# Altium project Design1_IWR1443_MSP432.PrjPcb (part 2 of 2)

## Sheet Design1_HighVoltage.SchDoc: High Voltage Management
size 431 x 279 mm; Date: Not shown in title block; ApprovedBy: Not shown in title block; CheckedBy: Not shown in title block; Author: Not shown in title block; CompanyName: Not shown in title block; DrawnBy: Joe Quintal; Engineer: Not shown in title block; Organization: Not shown in title block; Address1: Not shown in title block; Address2: Not shown in title block; Address3: Not shown in title block; Address4: Not shown in title block; DocumentNumber: 5; Revision: Use project parameter SCH_Rev; SheetNumber: 5; SheetTotal: 6; PageSetup: Record=PageOptions¦CenterHorizontal=True¦CenterVertical=True¦PrintScale=0.64¦XCorrection=1.00¦YCorrection=1.00¦PrintKind=0¦BorderSize=5000000¦LeftOffset=0¦BottomOffset=0¦Orientation=2¦PaperLength=1000¦PaperWidth=1000¦Scale=100¦PaperSource=15¦PrintQuality=600¦MediaType=1¦DitherType=10¦PrintScaleMode=1¦PaperKind=Letter
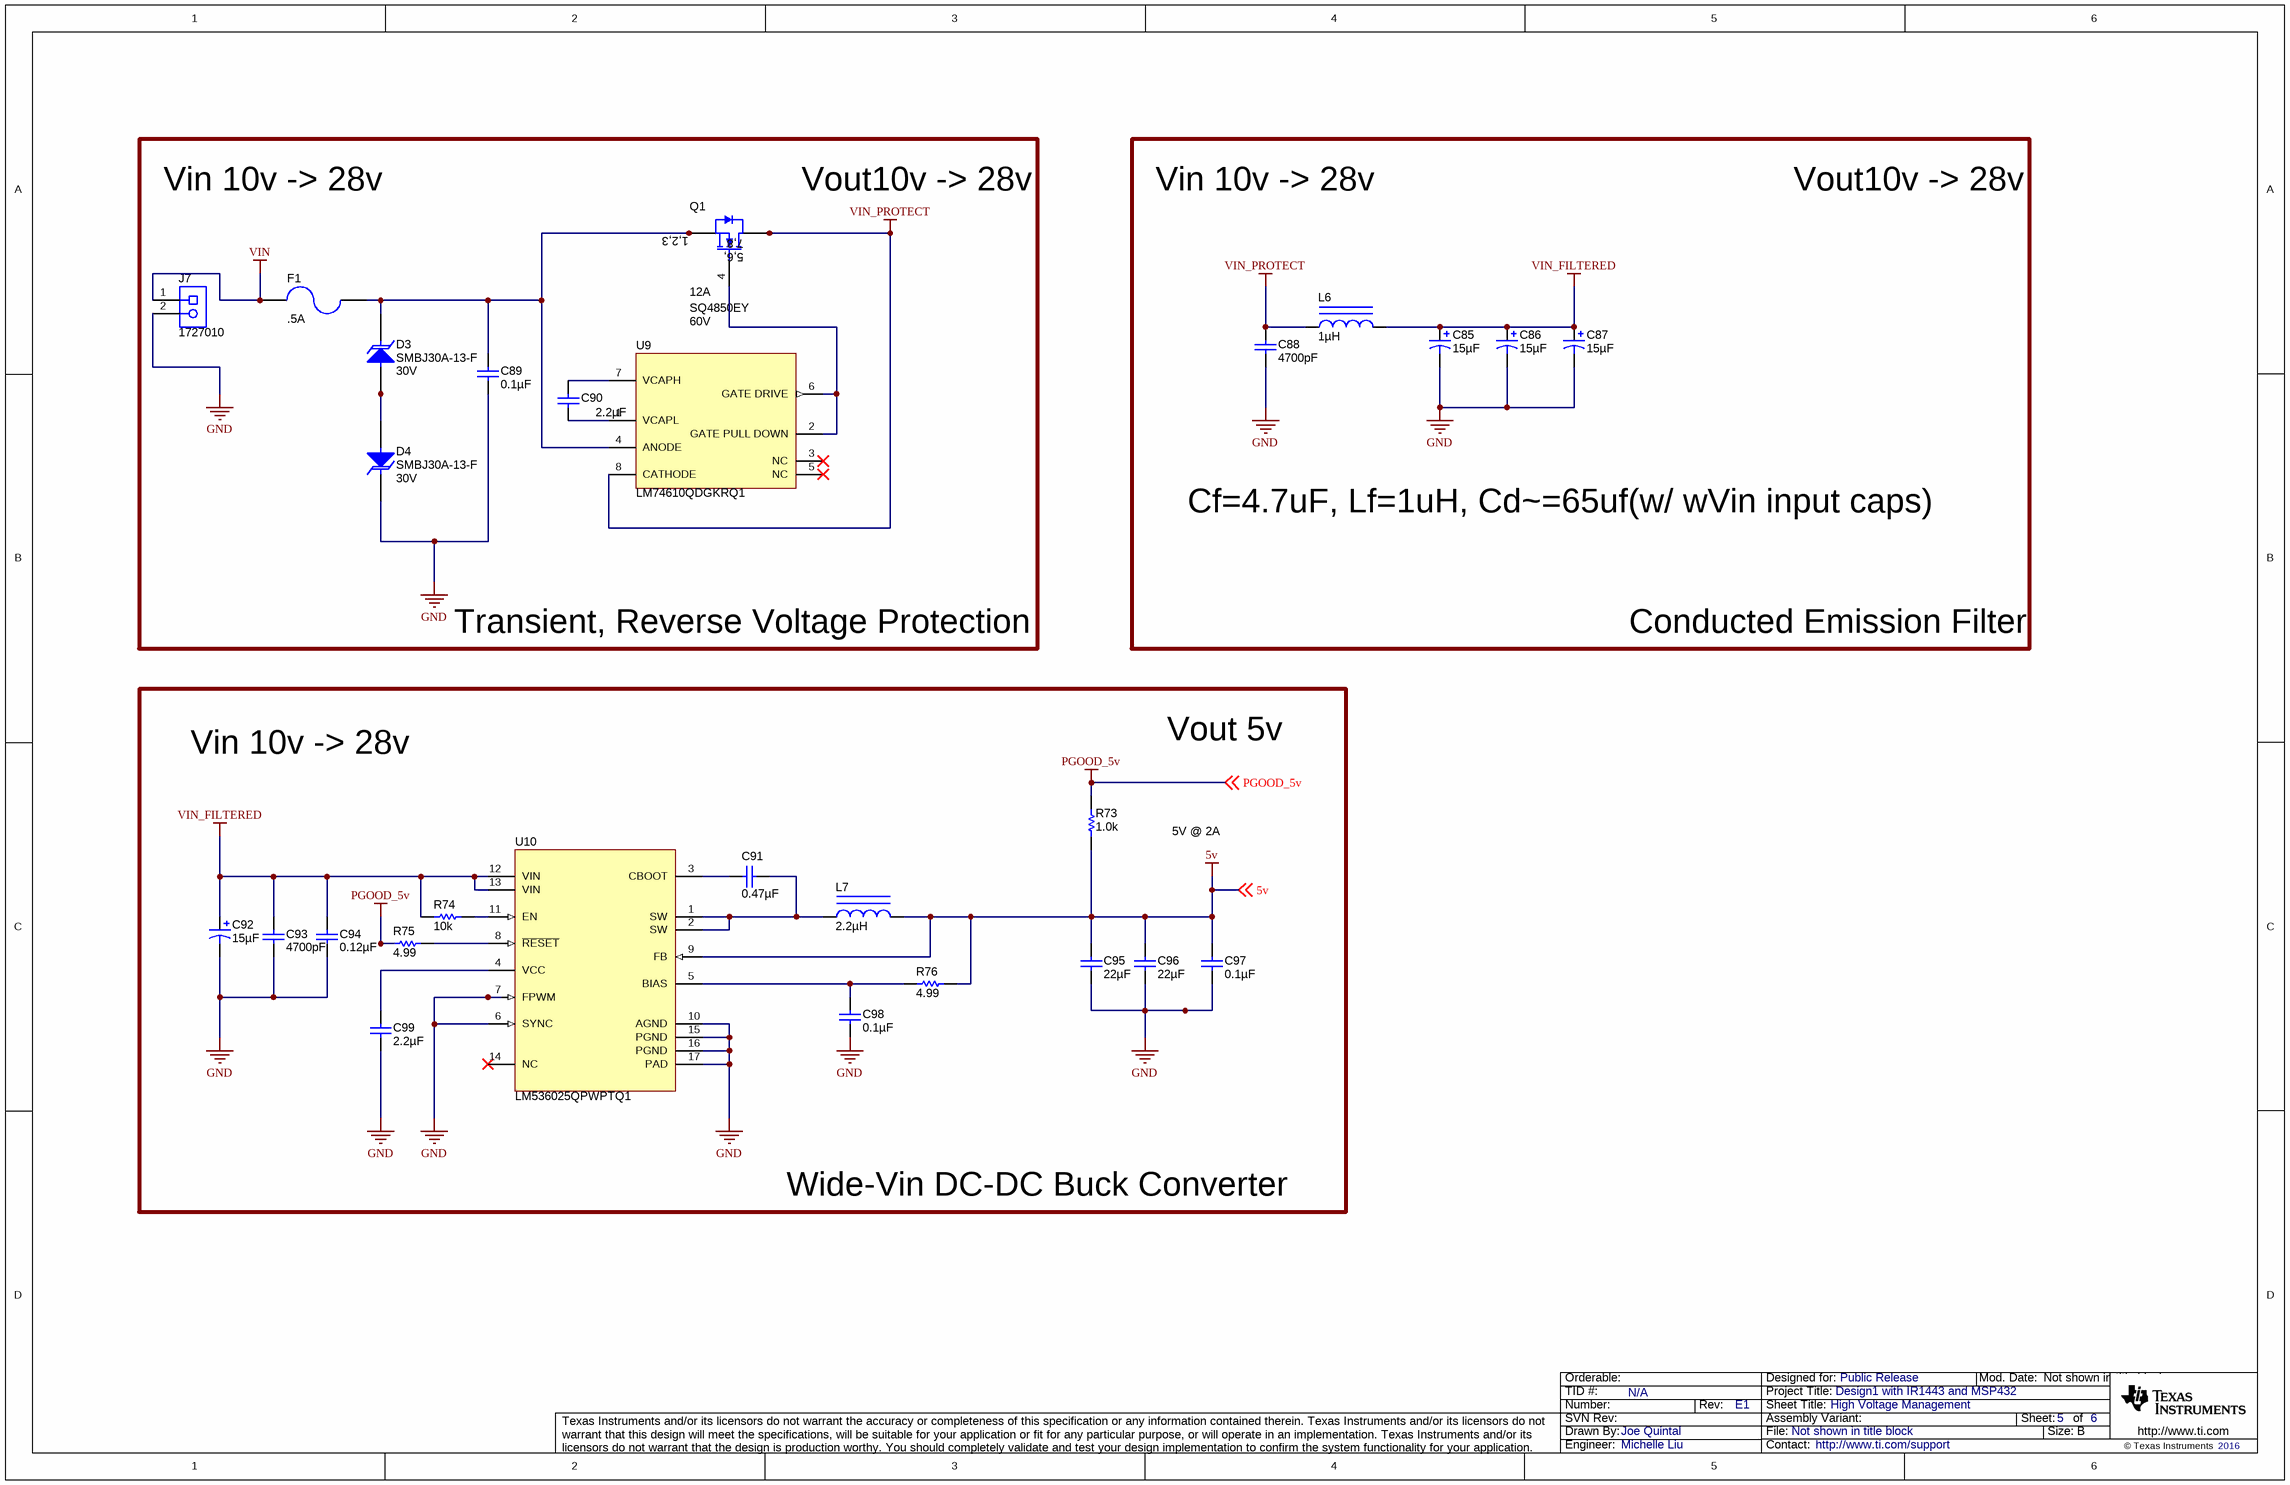
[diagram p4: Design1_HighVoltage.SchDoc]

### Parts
C85  ValueDisplayed: 15µF  [CC_CASER]  (hidden comment: TPSE156M050T0250V)
C86  ValueDisplayed: 15µF  [CC_CASER]  (hidden comment: TPSE156M050T0250V)
C87  ValueDisplayed: 15µF  [CC_CASER]  (hidden comment: TPSE156M050T0250V)
C88  ValueDisplayed: 4700pF  [0603]  (hidden comment: 885012206087)
C89  ValueDisplayed: 0.1µF  [0805_145]  (hidden comment: CEU4J2X7R1H104K125AE)
C90  ValueDisplayed: 2.2µF  [0603]  (hidden comment: GRM188R71A225KE15D)
C91  ValueDisplayed: 0.47µF  [0603S]  (hidden comment: GRM188R71E474KA12D)
C92  ValueDisplayed: 15µF  [CC_CASER]  (hidden comment: TPSE156M050T0250V)
C93  ValueDisplayed: 4700pF  [0805_HV]  (hidden comment: 08055C472JAT2A)
C94  ValueDisplayed: 0.12µF  [0805_HV]  (hidden comment: 08055C124KAT2A)
C95  ValueDisplayed: 22µF  [0805_HV]  (hidden comment: EMK212BBJ226MG-T)
C96  ValueDisplayed: 22µF  [0805_HV]  (hidden comment: EMK212BBJ226MG-T)
C97  ValueDisplayed: 0.1µF  [0402]  (hidden comment: GRM155R61C104KA88D)
C98  ValueDisplayed: 0.1µF  [0402S]  (hidden comment: GCM155R7IC104KA55D)
C99  ValueDisplayed: 2.2µF  [0603S]  (hidden comment: GRM188R71A225KE15D)
D3  SMBJ30A-13-F  value 30V  [SMB]
D4  SMBJ30A-13-F  value 30V  [SMB]
F1  .5A  [1812]
J7  1727010  [PhoenixConact_1727010]
L6  ValueDisplayed: 1µH  [IFSC-0806AZ-01]  (hidden comment: IFSC0806AZER1R0M01)
L7  ValueDisplayed: 2.2µH  [IHLP-2020BZ]  (hidden comment: IHLP2020BZER2R2M01)
Q1  12A  value 60V  [SO-8]
R73  ValueDisplayed: 1.0k  [0603]  (hidden comment: CRCW06031K00JNEA)
R74  ValueDisplayed: 10k  [0402S]  (hidden comment: CRCW040210K0JNED)
R75  ValueDisplayed: 4.99  [0402S]  (hidden comment: CRCW04024R99FKED)
R76  ValueDisplayed: 4.99  [0402S]  (hidden comment: CRCW04024R99FKED)
U9  LM74610QDGKRQ1  [DGK0008A_N]
U10  LM536025QPWPTQ1  [PWP0016H_N]

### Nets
5v: C95.1 C96.1 C97.1 L7.2 R73.1 R76.2 U10.9(FB) ; off-sheet 5v
GND: C85.2(-) C86.2(-) C87.2(-) C88.2 C89.2 C92.2(-) C93.1 C94.2 C95.2 C96.2 C97.2 C98.2 C99.2 D4.1(K) J7.2 U10.6(SYNC) U10.7(FPWM) U10.10(AGND) U10.15(PGND) U10.16(PGND) U10.17(PAD)
PGOOD_5v: R73.2 R75.1 ; off-sheet PGOOD_5v
VIN: F1.2 J7.1
VIN_FILTERED: C85.1(+) C86.1(+) C87.1(+) C92.1(+) C93.2 C94.1 L6.2 R74.1 U10.12(VIN) U10.13(VIN)
VIN_PROTECT: C88.1 L6.1 Q1.5(D) Q1.6(D) Q1.7(D) Q1.8(D) U9.8(CATHODE)
NetC89_1: C89.1 D3.1(K) F1.1 Q1.1(S) Q1.2(S) Q1.3(S) U9.4(ANODE)
NetC90_1: C90.1 U9.7(VCAPH)
NetC90_2: C90.2 U9.1(VCAPL)
NetC91_1: C91.1 L7.1 U10.1(SW) U10.2(SW)
NetC91_2: C91.2 U10.3(CBOOT)
NetC98_1: C98.1 R76.1 U10.5(BIAS)
NetC99_1: C99.1 U10.4(VCC)
NetD3_2: D3.2(A) D4.2(A)
NetQ1_4: Q1.4(G) U9.2(GATE_PULL_DOWN) U9.6(GATE_DRIVE)
NetR74_2: R74.2 U10.11(EN)
NetR75_2: R75.2 U10.8(~{RESET})

Not connected (* = marked no-connect by the designer): U9 3(NC)* 5(NC)*; U10 14(NC)*

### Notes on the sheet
- Vin 10v -> 28v
- Vout10v -> 28v
- Cf=4.7uF, Lf=1uH, Cd~=65uf(w/ wVin input caps)
- Transient, Reverse Voltage Protection
- Conducted Emission Filter
- Vout 5v
- 5V @ 2A
- Wide-Vin DC-DC Buck Converter

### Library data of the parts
C85-C87 C92 = 595D226X0050R2T: CAP, TA, 15 µF, 50 V, +/- 20%, 0.25 ohm, SMD; Manufacturer: AVX; Polarized: Y; CompType: Capacitor; Value: 22uF; U/M: EA; Cap_F: 0.000022; Tolerance_%: 20; Value1: 0.39 ohm; VDC_V: 50; Value2: 50V; ESR_ohm: .25; TaMin_C: -55; TaMax_C: 85; Cap_Case: E; SizeAreaWB_mm2: 73.6; SizeArea_mm2: 43.2; SizeX_mm: 7.2; SizeY_mm: 6; SizeZ_mm: 3.5
C88 = 885012206087: CAP, CERM, 4700 pF, 50 V, +/- 10%, X7R, 0603; Manufacturer: Wurth Elektronik; Polarized: N; CompType: Capacitor; Value: 4700pF; U/M: EA; Cap_F: 0.0000000047; Tolerance_%: 10; Value1: Unknown; VDC_V: 50; Value2: 50V; TaMin_C: -55; TaMax_C: 125; SizeArea_mm2: 1.28; SizeAreaWB_mm2: 4.68; SizeX_mm: 1.6; SizeY_mm: 0.8; SizeZ_mm: 1; AEC Category: Q200
C89 = CEU4J2X7R1H104K125AE: CAP, CERM, 0.1 µF, 50 V, +/- 10%, X7R, 0805; Manufacturer: TDK; Polarized: N; CompType: Capacitor; Value: 0.1uF; U/M: EA; Cap_F: 0.0000001; Tolerance_%: 10; Value1: Unknown; VDC_V: 50; Value2: 50V; TaMin_C: -55; TaMax_C: 125; Cap_Case: 0805
C90 = GRM188R71A225KE15D: CAP, CERM, 2.2 µF, 10 V, +/- 10%, X7R, 0603; Manufacturer: MuRata; Polarized: N; CompType: Capacitor; Value: 2.2uF; U/M: EA; Cap_F: 0.0000022; Tolerance_%: 10; ESR_ohm: 0.009; Value1: 0.009 ohm; Value2: 10V; TaMin_C: -55; TaMax_C: 125
C91 = GRM188R71E474KA12D: CAP, CERM, 0.47 µF, 25 V, +/- 10%, X7R, 0603; Manufacturer: MuRata; Polarized: N; CompType: Capacitor; Value: 0.47uF; U/M: EA; Cap_F: 0.00000047; Tolerance_%: 10; Value1: Unknown; VDC_V: 25; Value2: 25V; TaMin_C: -55; TaMax_C: 125; Cap_Case: 0603
C93 = 08055C472JAT2A: CAP, CERM, 4700 pF, 50 V, +/- 5%, X7R, 0805; Manufacturer: AVX; Polarized: N; CompType: Capacitor; Value: 4700pF; U/M: EA; Cap_F: 0.0000000047; Tolerance_%: 5; ESR_ohm: 0.119; Value1: 0.119 ohm; VDC_V: 50; Value2: 50V; TaMin_C: -55; TaMax_C: 125; Cap_Case: 0805; SizeArea_mm2: 2.5; SizeAreaWB_mm2: 6.75; SizeX_mm: 2; SizeY_mm: 1.25; SizeZ_mm: 1.45; AEC Category: Q200
C94 = 08055C124KAT2A: CAP, CERM, 0.12 µF, 50 V, +/- 10%, X7R, 0805; Manufacturer: AVX; Polarized: N; CompType: Capacitor; Value: 0.12uF; U/M: EA; Cap_F: 0.00000012; Tolerance_%: 10; ESR_ohm: 0.022; Value1: 0.022 ohm; VDC_V: 50; Value2: 50V; TaMin_C: -55; TaMax_C: 125; Cap_Case: 0805; SizeArea_mm2: 2.5; SizeAreaWB_mm2: 6.75; SizeX_mm: 2; SizeY_mm: 1.25; SizeZ_mm: 1.45; AEC Category: Q200
C95 C96 = EMK212BBJ226MG-T: CAP, CERM, 22 µF, 16 V, +/- 20%, X5R, 0805; Manufacturer: Taiyo Yuden; Polarized: N; CompType: Capacitor; Value: 22uF; U/M: EA; Cap_F: 0.000022; Tolerance_%: 20; Value1: Unknown; VDC_V: 16; Value2: 16V; TaMin_C: -55; TaMax_C: 85; Cap_Case: 0805; SizeArea_mm2: 2.5; SizeAreaWB_mm2: 6.75; SizeX_mm: 2; SizeY_mm: 1.25; SizeZ_mm: 1.45; AEC Category: Q200
C97 = GRM155R61C104KA88D: CAP, CERM, 0.1 µF, 16 V, +/- 10%, X5R, 0402; Manufacturer: MuRata; Polarized: N; CompType: Capacitor; Value: 0.1uF; U/M: EA; Cap_F: 0.0000001; Tolerance_%: 10; Value1: Unknown; VDC_V: 16; Value2: 16V; TaMin_C: -55; TaMax_C: 85; SizeArea_mm2: 0.5; SizeAreaWB_mm2: 3; SizeX_mm: 1; SizeZ_mm: 0.6; AEC Category: Q200
C98 = GCM155R7IC104KA55D: CAP, CERM, 0.1 µF, 16 V, +/- 10%, X7R, 0402; Manufacturer: MuRata; Polarized: N; CompType: Capacitor; Value: 0.1uF; U/M: EA; Cap_F: 0.0000001; Tolerance_%: 10; Value1: Unknown; VDC_V: 16; Value2: 16V; TaMin_C: -55; TaMax_C: 125; Cap_Case: 0402
C99 = GRM188R71A225KE15D: CAP, CERM, 2.2 µF, 10 V, +/- 10%, X7R, 0603; Manufacturer: MuRata; Polarized: N; CompType: Capacitor; Value: 2.2uF; U/M: EA; Cap_F: 0.0000022; Tolerance_%: 10; ESR_ohm: 0.009; Value1: 0.009 ohm; Value2: 10V; TaMin_C: -55; TaMax_C: 125; Cap_Case: 0603
D3 D4 = SMBJ30A-13-F: Diode, TVS, Uni, 30 V, 48.4 Vc, SMB; Manufacturer: Diodes Inc.; U/M: EA; Power_W: 5; Vr_V: 30; Value1: 5W; SizeAreaWB_mm2: 44.156; SizeArea_mm2: 21.336; SizeX_mm: 5.6; SizeY_mm: 3.81; SizeZ_mm: 2.6; AEC Category: Q101
F1 = 0ZCC0075BF2B: Fuse, 0.75 A, 33 VDC, SMD; Manufacturer: Bel Fuse; SizeAreaWB_mm2: 23.1; SizeArea_mm2: 14.4; SizeX_mm: 4.5; SizeY_mm: 3.2; SizeZ_mm: 1.35; VDC_V: 33; Irating_A: 0.75; Rtyp_Ohm: 0.18
J7 = 1727010: Conn Term Block, 2POS, 3.81mm, TH; Manufacturer: Phoenix Contact; SymbolCreator: a0412235; CompType: Terminal Block; U/M: EA; Value: 2x1
L6 = IFSC0806AZER1R0M01: Inductor, Shielded, Ferrite, 1 µH, 1.6 A, 0.115 ohm, SMD; Manufacturer: Vishay-Dale; Value: 1uH; Ind_H: 1.0E-6; Imax_A: 1.6; Irms: 1.6A @ 40C rise; Isat: 1.88A @ 30% inductance drop; DCR_ohm: 0.115; Value2: 1.6A; SizeAreaWB_mm2: 7.8; SizeArea_mm2: 3.2; SizeX_mm: 2; SizeZ_mm: 1; AEC Category: Q200
L7 = IHLP2020BZER2R2M01: Inductor, Shielded Drum Core, Powdered Iron, 2.2 µH, 4.2 A, 0.0456 ohm, SMD; Manufacturer: Vishay-Dale; Value: 2.2uH; Ind_H: 2.2E-6; Imax_A: 4.2; Irms: 4.2A @ 40C rise; Isat: 12.5A @ 20% inductance drop; DCR_ohm: 0.0456; Value2: 4.2A; SizeAreaWB_mm2: 53.7782; SizeArea_mm2: 28.4382; SizeX_mm: 5.49; SizeY_mm: 5.18; SizeZ_mm: 2; AEC Category: Q200
Q1 = SQ4850EY: MOSFET, N-CH, 60 V, 12 A, SO-8; Manufacturer: Vishay-Siliconix; Alternate Manufacturer: None; U/M: EA; ChType: N; VdsMax_V: 60; Value1: 0.031 ohm; Rdson45_ohm: 0.031; Value2: 20 nC; QgTyp_nC: 20; IdsMax_A: 12
R73 = CRCW06031K00JNEA: RES, 1.0 k, 5%, 0.1 W, 0603; Manufacturer: Vishay-Dale; CompType: Resistor; Value: 1.0k; Res_ohm: 1000; Value_Code: 1k00; Tolerance_%: 5; Power_W: 0.1; Value2: 0.1W; VDC_V: 75; TempCo: 200 ppm/C; SizeArea_mm2: 1.28; SizeX_mm: 1.6; SizeY_mm: 0.8; SizeZ_mm: 1; EIA_Code: E24; U/M: EA; AEC Category: Q200
R74 = CRCW040210K0JNED: RES, 10 k, 5%, 0.063 W, 0402; Manufacturer: Vishay-Dale; CompType: Resistor; Value: 10k; Res_ohm: 10000; Value_Code: 10k0; Tolerance_%: 5; Power_W: 0.063; Value2: 0.063W; VDC_V: 50; TempCo: 200 ppm/C; EIA_Code: E24; U/M: EA
R75 R76 = CRCW04024R99FKED: RES, 4.99, 1%, 0.063 W, 0402; Manufacturer: Vishay-Dale; CompType: Resistor; Value: 4.99; Value_Code: 4R99; Tolerance_%: 1; Power_W: 0.063; Value2: 0.063W; VDC_V: 50; TempCo: 100 ppm/C; EIA_Code: E96; U/M: EA
U9 = LM74610QDGKRQ1: Smart Diode Controller, DGK0008A; Manufacturer: Texas Instruments; SymbolCreator: Altium; CompType: IC; U/M: EA
U10 = LM536033QPWPQ1: 5V, 2A, Buck Regulator For Automotive Applications, PWP0016H; Manufacturer: Texas Instruments; SymbolCreator: Altium; CompType: IC; U/M: EA

## Sheet Design1_EVM_Hardware.SchDoc
size 431 x 279 mm; Date: Not shown in title block; ApprovedBy: Not shown in title block; CheckedBy: Not shown in title block; Author: Not shown in title block; CompanyName: Not shown in title block; Engineer: Not shown in title block; Organization: Not shown in title block; Address1: Not shown in title block; Address2: Not shown in title block; Address3: Not shown in title block; Address4: Not shown in title block; DocumentNumber: 6; Revision: Use project parameter SCH_Rev; SheetNumber: 6; SheetTotal: 6; PageSetup: Record=PageOptions¦CenterHorizontal=True¦CenterVertical=True¦PrintScale=1.00¦XCorrection=1.00¦YCorrection=1.00¦PrintKind=0¦BorderSize=5000000¦LeftOffset=0¦BottomOffset=0¦Orientation=2¦PaperLength=1000¦PaperWidth=1000¦Scale=100¦PaperSource=15¦PrintQuality=600¦MediaType=1¦DitherType=10¦PaperKind=Letter¦PrintScaleMode=1
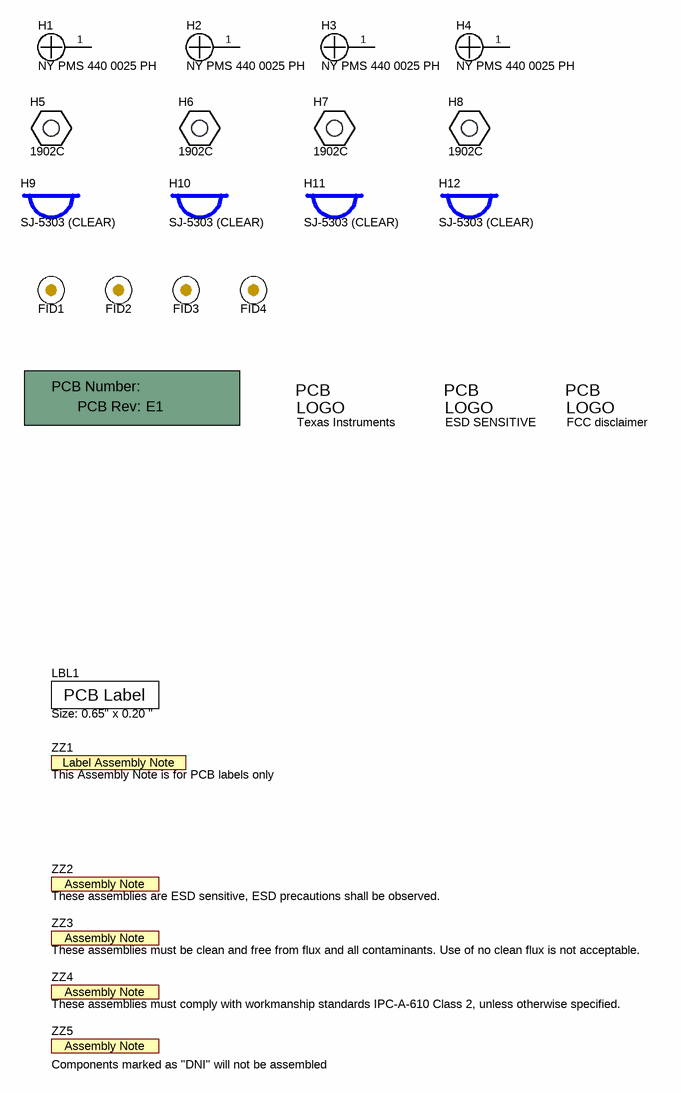
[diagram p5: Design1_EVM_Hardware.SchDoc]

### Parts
!PCB1  Printed Circuit Board  (value not drawn)  (mechanical)
FID1  Fiducial  [Fiducial10-20]  (value not drawn)
FID2  Fiducial  [Fiducial10-20]  (value not drawn)
FID3  Fiducial  [Fiducial10-20]  (value not drawn)
FID4  Fiducial  [Fiducial10-20]  (value not drawn)
H1  NY PMS 440 0025 PH  [NY PMS 440 0025 PH]
H2  NY PMS 440 0025 PH  [NY PMS 440 0025 PH]
H3  NY PMS 440 0025 PH  [NY PMS 440 0025 PH]
H4  NY PMS 440 0025 PH  [NY PMS 440 0025 PH]
H5  1902C  [Keystone_1902C]
H6  1902C  [Keystone_1902C]
H7  1902C  [Keystone_1902C]
H8  1902C  [Keystone_1902C]
H9  SJ-5303 (CLEAR)  [Bumpon_SJ5003Transparent]
H10  SJ-5303 (CLEAR)  [Bumpon_SJ5003Transparent]
H11  SJ-5303 (CLEAR)  [Bumpon_SJ5003Transparent]
H12  SJ-5303 (CLEAR)  [Bumpon_SJ5003Transparent]
LBL1  Size: 0.65" x 0.20 "  [Label_650x200]
Logo1  Texas Instruments  [TI_Stacked_Overlay_Small]  (no BOM)
Logo2  ESD SENSITIVE  [Pb-Free_Overlay_Small]  (no BOM)
Logo3  FCC disclaimer  [FCC_disclaimer]  (no BOM)
ZZ1  This Assembly Note is for PCB labels only  [AssemblyNoteLabel]  (no BOM)
ZZ2  These assemblies are ESD sensitive, ESD precautions shall be observed.  [AssemblyNote]  (no BOM)
ZZ3  These assemblies must be clean and free from flux and all contaminants. Use of no clean flux is not acceptable.  [AssemblyNote]  (no BOM)
ZZ4  These assemblies must comply with workmanship standards IPC-A-610 Class 2, unless otherwise specified.  [AssemblyNote]  (no BOM)
ZZ5  Components marked as "DNI" will not be assembled  [AssemblyNote]  (no BOM)

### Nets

Not connected (* = marked no-connect by the designer): H1 1; H2 1; H3 1; H4 1

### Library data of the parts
!PCB1 = PCB: Manufacturer: Any; SymbolCreator: a0412235
FID1-FID4 = Fiducial: Fiducial mark.  There is nothing to buy or mount.; SymbolCreator: codlsc
H1-H4 = NY PMS 440 0025 PH: Machine Screw, Round, #4-40 x 1/4, Nylon, Philips panhead; Manufacturer: B&F Fastener Supply; CompType: Hardware; SymbolCreator: codlsc; U/M: EA
H5-H8 = 1902C: Standoff, Hex, 0.5"L #4-40 Nylon; Manufacturer: Keystone; CompType: Hardware
H9-H12 = SJ-5303 (CLEAR): Bumpon, Hemisphere, 0.44 X 0.20, Clear; Manufacturer: 3M; SymbolCreator: a0412235
LBL1 = THT-14-423-10: Thermal Transfer Printable Labels, 0.650" W x 0.200" H - 10,000 per roll; Manufacturer: Brady; SymbolCreator: a0412235; CompType: Label
Logo1 = TI_Logo: Texas Instrument Corporate Signature; SymbolCreator: codlsc
Logo2 = Pb-Free: Pb-Free Symbol; SymbolCreator: a0412235
Logo3 = FCC_disclaimer: SymbolCreator: codlsc
ZZ1 = AssemblyNoteLabel: SymbolCreator: a0412235
ZZ2-ZZ5 = AssemblyNote: SymbolCreator: codlsc

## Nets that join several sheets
1.2V: Design1_IWR1443_interfaces (10 pins), Design1_LowVoltage (C47.1 C48.1 L3.2 U5.14)
1.8V: Design1_IWR1443_interfaces (9 pins), Design1_LowVoltage (7 pins)
1.35V_RF1: Design1_IWR1443_interfaces (5 pins), Design1_LowVoltage (7 pins)
1.35V_RF2: Design1_IWR1443_interfaces (C13.1 C14.1 U1.C2 U1.D2), Design1_LowVoltage (7 pins)
3.3V: Design1_IWR1443_interfaces (16 pins), Design1_MSP432 (7 pins), Design1_LowVoltage (9 pins)
5v: Design1_IWR1443_interfaces (R21.1), Design1_LowVoltage (18 pins), Design1_HighVoltage (7 pins)
EN1: Design1_MSP432 (U4.49), Design1_LowVoltage (R57.1 R63.1 U5.7)
EN2: Design1_MSP432 (U4.50), Design1_LowVoltage (R58.1 U5.15)
EN3: Design1_MSP432 (U4.51), Design1_LowVoltage (R60.1 U5.2)
GND: Design1_IWR1443_interfaces (112 pins), Design1_MSP432 (13 pins), Design1_LowVoltage (69 pins), Design1_HighVoltage (21 pins)
MISO: Design1_IWR1443_interfaces (R11.2 U1.P5), Design1_MSP432 (U4.11)
MOSI: Design1_IWR1443_interfaces (R16.2 U1.R8), Design1_MSP432 (U4.10)
nINT: Design1_MSP432 (U4.21), Design1_LowVoltage (R62.1 U5.19)
PGOOD_5v: Design1_LowVoltage (R64.1 R65.1), Design1_HighVoltage (R73.2 R75.1)
SCL: Design1_MSP432 (U4.3), Design1_LowVoltage (R45.1 U5.5)
SDA: Design1_MSP432 (U4.2), Design1_LowVoltage (R66.1 U5.6)
IR_CLK: Design1_IWR1443_interfaces (U1.R9), Design1_MSP432 (U4.9)
IR_CS: Design1_IWR1443_interfaces (U1.R7), Design1_MSP432 (U4.32)
IR_GPIO0__P4.6: Design1_IWR1443_interfaces (R14.1 U1.N4), Design1_MSP432 (U4.62)
IR_GPIO1__P5.7: Design1_IWR1443_interfaces (U1.N7), Design1_MSP432 (U4.71)
IR_GPIO2__P5.2: Design1_IWR1443_interfaces (U1.N13), Design1_MSP432 (U4.66)
IR_HOSTINTR__P5.0: Design1_IWR1443_interfaces (R6.2 U1.P6), Design1_MSP432 (U4.64)
IR_NRST_MCU: Design1_IWR1443_interfaces (R8.1), Design1_MSP432 (U4.63)
IR_NRST_XDS: Design1_IWR1443_interfaces (R9.1), Design1_MSP432 (R42.2)
IR_PMIC_CLKOUT_SOP2__P5.5: Design1_IWR1443_interfaces (R19.2 U1.P13), Design1_MSP432 (U4.69)
IR_RS232_RX__P3.3: Design1_IWR1443_interfaces (U1.N5), Design1_MSP432 (U4.35)
IR_RS232_TX__P3.2: Design1_IWR1443_interfaces (U1.N6), Design1_MSP432 (U4.34)
IR_SYNC_OUT_SOP1__P4.5: Design1_IWR1443_interfaces (R24.2 U1.P11), Design1_MSP432 (U4.61)
IR_SYNCIN__P4.1: Design1_IWR1443_interfaces (U1.N10), Design1_MSP432 (U4.57)
MCU_SOP0: Design1_IWR1443_interfaces (R27.2), Design1_MSP432 (U4.39)
MCU_SOP1: Design1_IWR1443_interfaces (R23.2), Design1_MSP432 (U4.37)
MCU_SOP2: Design1_IWR1443_interfaces (R18.2), Design1_MSP432 (U4.65)
MSP_~{RST}: Design1_MSP432 (R41.2 U4.83), Design1_LowVoltage (5 pins)
MSP_TDI: Design1_IWR1443_interfaces (R2.2), Design1_MSP432 (R40.2 U4.92)
MSP_TDO: Design1_IWR1443_interfaces (R4.2), Design1_MSP432 (R39.2 U4.93)
NERROR_IN__P2.6: Design1_IWR1443_interfaces (U1.P7), Design1_MSP432 (U4.22)
NERROR_OUT__P2.7: Design1_IWR1443_interfaces (U1.N8), Design1_MSP432 (U4.23)
TCK: Design1_IWR1443_interfaces (U1.M13), Design1_MSP432 (J6.4 U4.95)
TDI: Design1_IWR1443_interfaces (R5.2), Design1_MSP432 (J6.8 R40.1)
TDO: Design1_IWR1443_interfaces (R3.2), Design1_MSP432 (J6.6 R39.1)
TMS: Design1_IWR1443_interfaces (U1.L13), Design1_MSP432 (J6.2 U4.94)

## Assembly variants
001: not fitted FID1 FID2 FID3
